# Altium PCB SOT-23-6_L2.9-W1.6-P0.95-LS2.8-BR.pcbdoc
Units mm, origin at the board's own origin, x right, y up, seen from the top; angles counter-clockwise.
Board outline 16.5 x 16.03 mm, 2 copper layers (Top Layer, Bottom Layer), stack 0 mm thick; 1 components, 0 nets, 6 pads, 0 vias.
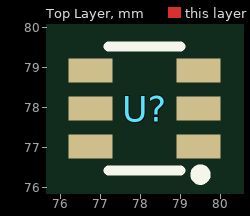
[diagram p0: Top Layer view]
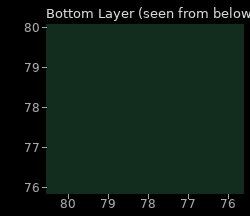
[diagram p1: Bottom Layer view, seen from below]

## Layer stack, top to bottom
Top Layer: signal copper (thickness not stored)
Bottom Layer: signal copper (thickness not stored)

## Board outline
86.35,69.85 69.85,69.85 69.85,85.878 86.35,85.878

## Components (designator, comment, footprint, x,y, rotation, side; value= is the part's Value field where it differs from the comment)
U? "" SOT-23-6_L2.9-W1.6-P0.95-LS2.8-BR 78.1,77.978 r0 top

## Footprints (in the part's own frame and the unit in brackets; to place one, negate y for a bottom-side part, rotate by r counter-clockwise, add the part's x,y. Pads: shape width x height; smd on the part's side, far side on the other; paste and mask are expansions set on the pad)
SOT-23-6_L2.9-W1.6-P0.95-LS2.8-BR [mm]
  rect 1.1x0.6 smd paste+0 mask+0.051: 1(1.35,-0.95) 2(1.35,0) 3(1.35,0.95) 4(-1.35,0.95) 5(-1.35,0) 6(-1.35,-0.95)
  silkscreen extent -0.9,-1.78 1.52,1.55

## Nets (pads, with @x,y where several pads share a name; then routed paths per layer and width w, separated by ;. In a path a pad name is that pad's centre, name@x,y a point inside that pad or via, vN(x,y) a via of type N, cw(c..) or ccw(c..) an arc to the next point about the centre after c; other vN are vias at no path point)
pads on no net: U?.1 U?.2 U?.3 U?.4 U?.5 U?.6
